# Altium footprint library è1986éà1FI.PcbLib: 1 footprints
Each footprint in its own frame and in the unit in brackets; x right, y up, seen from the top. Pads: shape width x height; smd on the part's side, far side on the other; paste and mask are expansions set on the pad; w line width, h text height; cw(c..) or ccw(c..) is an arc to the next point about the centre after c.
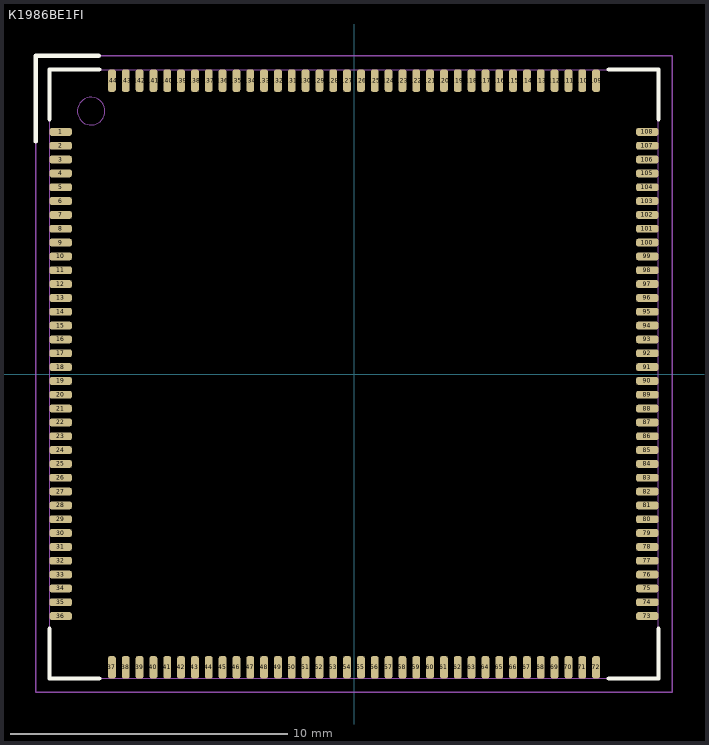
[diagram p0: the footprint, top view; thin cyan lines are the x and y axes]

## К1986ВЕ1FI [mm] "Package Type - QFN144 22x22x1,6 (0,5)"
height 1.6
pads (144):
  rrect50% 0.8x0.28 smd mask+0.05: 1(-10.6,8.75) 2(-10.6,8.25) 3(-10.6,7.75) 4(-10.6,7.25) 5(-10.6,6.75) 6(-10.6,6.25) 7(-10.6,5.75) 8(-10.6,5.25) 9(-10.6,4.75) 10(-10.6,4.25) 11(-10.6,3.75) 12(-10.6,3.25) 13(-10.6,2.75) 14(-10.6,2.25) 15(-10.6,1.75) 16(-10.6,1.25) 17(-10.6,0.75) 18(-10.6,0.25) 19(-10.6,-0.25) 20(-10.6,-0.75) 21(-10.6,-1.25) 22(-10.6,-1.75) 23(-10.6,-2.25) 24(-10.6,-2.75) 25(-10.6,-3.25) 26(-10.6,-3.75) 27(-10.6,-4.25) 28(-10.6,-4.75) 29(-10.6,-5.25) 30(-10.6,-5.75) 31(-10.6,-6.25) 32(-10.6,-6.75) 33(-10.6,-7.25) 34(-10.6,-7.75) 35(-10.6,-8.25) 36(-10.6,-8.75) 73(10.6,-8.75) 74(10.6,-8.25) 75(10.6,-7.75) 76(10.6,-7.25) 77(10.6,-6.75) 78(10.6,-6.25) 79(10.6,-5.75) 80(10.6,-5.25) 81(10.6,-4.75) 82(10.6,-4.25) 83(10.6,-3.75) 84(10.6,-3.25) 85(10.6,-2.75) 86(10.6,-2.25) 87(10.6,-1.75) 88(10.6,-1.25) 89(10.6,-0.75) 90(10.6,-0.25) 91(10.6,0.25) 92(10.6,0.75) 93(10.6,1.25) 94(10.6,1.75) 95(10.6,2.25) 96(10.6,2.75) 97(10.6,3.25) 98(10.6,3.75) 99(10.6,4.25) 100(10.6,4.75) 101(10.6,5.25) 102(10.6,5.75) 103(10.6,6.25) 104(10.6,6.75) 105(10.6,7.25) 106(10.6,7.75) 107(10.6,8.25) 108(10.6,8.75)
  rrect50% 0.28x0.8 smd mask+0.05: 37(-8.75,-10.6) 38(-8.25,-10.6) 39(-7.75,-10.6) 40(-7.25,-10.6) 41(-6.75,-10.6) 42(-6.25,-10.6) 43(-5.75,-10.6) 44(-5.25,-10.6) 45(-4.75,-10.6) 46(-4.25,-10.6) 47(-3.75,-10.6) 48(-3.25,-10.6) 49(-2.75,-10.6) 50(-2.25,-10.6) 51(-1.75,-10.6) 52(-1.25,-10.6) 53(-0.75,-10.6) 54(-0.25,-10.6) 55(0.25,-10.6) 56(0.75,-10.6) 57(1.25,-10.6) 58(1.75,-10.6) 59(2.25,-10.6) 60(2.75,-10.6) 61(3.25,-10.6) 62(3.75,-10.6) 63(4.25,-10.6) 64(4.75,-10.6) 65(5.25,-10.6) 66(5.75,-10.6) 67(6.25,-10.6) 68(6.75,-10.6) 69(7.25,-10.6) 70(7.75,-10.6) 71(8.25,-10.6) 72(8.75,-10.6) 109(8.75,10.6) 110(8.25,10.6) 111(7.75,10.6) 112(7.25,10.6) 113(6.75,10.6) 114(6.25,10.6) 115(5.75,10.6) 116(5.25,10.6) 117(4.75,10.6) 118(4.25,10.6) 119(3.75,10.6) 120(3.25,10.6) 121(2.75,10.6) 122(2.25,10.6) 123(1.75,10.6) 124(1.25,10.6) 125(0.75,10.6) 126(0.25,10.6) 127(-0.25,10.6) 128(-0.75,10.6) 129(-1.25,10.6) 130(-1.75,10.6) 131(-2.25,10.6) 132(-2.75,10.6) 133(-3.25,10.6) 134(-3.75,10.6) 135(-4.25,10.6) 136(-4.75,10.6) 137(-5.25,10.6) 138(-5.75,10.6) 139(-6.25,10.6) 140(-6.75,10.6) 141(-7.25,10.6) 142(-7.75,10.6) 143(-8.25,10.6) 144(-8.75,10.6)
Top Overlay:
  lines w0.15: -11.5,8.4 -11.5,11.5 -9.225,11.5 ; -11,-9.209 -11,-11 -9.209,-11 ; -11,9.209 -11,11 -9.209,11 ; 9.209,-11 11,-11 11,-9.209 ; 9.209,11 11,11 11,9.209
Top Assembly:
  circle w0: c-9.5,9.5 r0.5
  lines w0: -11,-11 11,-11 11,11 -11,11 -11,-11
  text ".Designator" at -2.618,-0.355 h1.52
Top Courtyard:
  lines w0.05: -11.5,-11.5 -11.5,11.5 11.5,11.5 11.5,-11.5 -11.5,-11.5
3D body "QFN50P2200X2200X170-144.STEP": height 1.7, standoff 0, extent -11,-11 11,11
